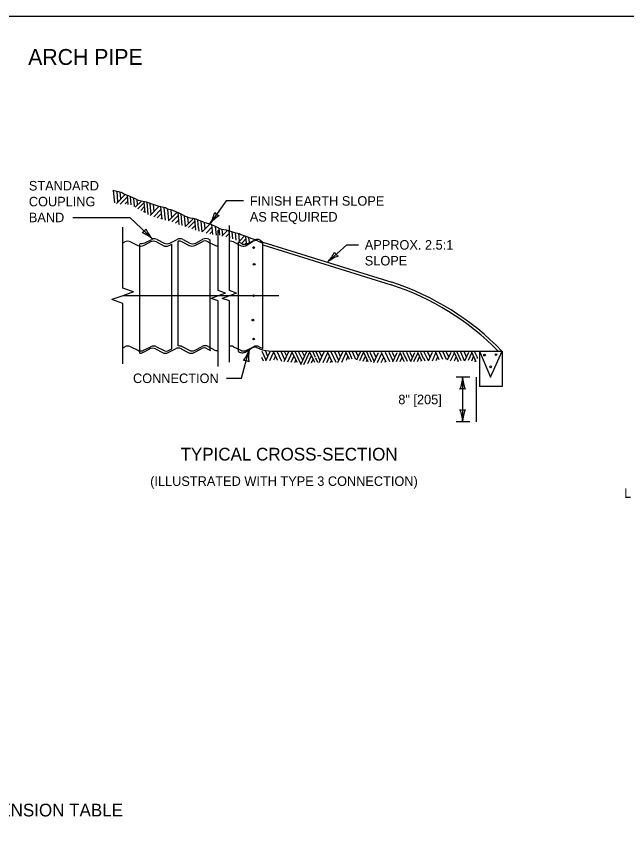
# Model space of a CAD drawing. Extents: x 49991.4 to 50021, y 49987.6 to 50011.4.
# Drawn here: x 50003.07 to 50006.92, y 49993.88 to 49999 of the extents above; entities that cross this region are included whole.
import ezdxf

# ---------------------------------------------------------------- set-up
doc = ezdxf.new("R2010")
doc.units = 0
for name, color, linetype in [('Level 1', 7, 'Continuous'), ('Level 2', 7, 'Continuous'), ('Level 3', 7, 'Continuous'), ('Level 4', 7, 'Continuous'), ('Level 5', 7, 'Continuous'), ('Level 6', 7, 'Continuous')]:
    doc.layers.add(name, color=color, linetype=linetype)

msp = doc.modelspace()

# ---------------------------------------------------------------- linework, layer by layer
at = {"layer": 'Level 1'}
for p, q in [((50003.6903, 49997.8225), (50003.6832, 49997.901)), ((50003.7012, 49997.8187), (50003.7579, 49997.8769)), ((50003.7109, 49997.8295), (50003.7049, 49997.8954)), ((50003.7292, 49997.8481), (50003.7252, 49997.8918)), ((50003.7755, 49997.8133), (50003.7702, 49997.87)), ((50003.7252, 49997.8141), (50003.7709, 49997.8607)), ((50003.7571, 49997.8164), (50003.7736, 49997.834)), ((50003.794, 49997.8104), (50003.7893, 49997.8613)), ((50003.8147, 49997.7995), (50003.8101, 49997.8529)), ((50003.82, 49997.7953), (50003.8584, 49997.8345)), ((50003.8347, 49997.8105), (50003.8318, 49997.844)), ((50003.8356, 49997.7853), (50003.8755, 49997.8256)), ((50003.8818, 49997.7611), (50003.8753, 49997.8285)), ((50003.8985, 49997.7802), (50003.8942, 49997.8244)), ((50003.92, 49997.7506), (50003.9133, 49997.8175)), ((50003.8546, 49997.7751), (50003.8785, 49997.8001)), ((50003.8727, 49997.7661), (50003.8803, 49997.7745)), ((50003.9016, 49997.7506), (50003.8992, 49997.7761)), ((50003.914, 49997.7445), (50003.97, 49997.8019)), ((50003.9381, 49997.769), (50003.9347, 49997.8124)), ((50003.9365, 49997.7359), (50003.9827, 49997.783)), ((50003.9886, 49997.7203), (50003.9806, 49997.7985)), ((50004.0106, 49997.7148), (50004.0027, 49997.7924)), ((50004.0321, 49997.7124), (50004.0253, 49997.7823)), ((50004.0285, 49997.7094), (50004.0834, 49997.7652)), ((50004.0499, 49997.7314), (50004.0455, 49997.7774)), ((50003.9587, 49997.7287), (50003.9853, 49997.7556)), ((50003.9819, 49997.7224), (50003.9874, 49997.7287)), ((50004.0507, 49997.7025), (50004.0911, 49997.7443)), ((50004.0735, 49997.6956), (50004.0942, 49997.717)), ((50004.097, 49997.6873), (50004.0898, 49997.7625)), ((50004.1159, 49997.6807), (50004.109, 49997.7514)), ((50004.1367, 49997.6738), (50004.13, 49997.7402)), ((50004.1361, 49997.6735), (50004.1865, 49997.7254)), ((50004.1555, 49997.6933), (50004.1517, 49997.7307)), ((50004.2016, 49997.6516), (50004.1955, 49997.7216)), ((50004.2189, 49997.6635), (50004.2146, 49997.7148)), ((50004.096, 49997.6878), (50004.0975, 49997.6894)), ((50004.1551, 49997.6669), (50004.1961, 49997.7091)), ((50004.1759, 49997.6598), (50004.1984, 49997.6832)), ((50004.2229, 49997.6456), (50004.2208, 49997.6652)), ((50004.2418, 49997.6398), (50004.2353, 49997.7065)), ((50004.2418, 49997.6398), (50004.2906, 49997.6902)), ((50004.2598, 49997.6584), (50004.2565, 49997.6974)), ((50004.2659, 49997.6328), (50004.3041, 49997.672)), ((50004.3088, 49997.6233), (50004.3027, 49997.6858)), ((50004.3305, 49997.619), (50004.3252, 49997.6747)), ((50004.3517, 49997.62), (50004.3474, 49997.6641)), ((50004.1972, 49997.653), (50004.201, 49997.6575)), ((50004.2896, 49997.627), (50004.3067, 49997.6444)), ((50004.3654, 49997.6129), (50004.4005, 49997.6496)), ((50004.3714, 49997.62), (50004.3682, 49997.6557)), ((50004.3893, 49997.6084), (50004.4133, 49997.6328)), ((50004.4165, 49997.6005), (50004.4117, 49997.6461)), ((50004.435, 49997.5958), (50004.4307, 49997.6399)), ((50004.456, 49997.5885), (50004.4515, 49997.6345)), ((50004.4769, 49997.5823), (50004.4727, 49997.6298)), ((50004.474, 49997.579), (50004.508, 49997.6144)), ((50004.5207, 49997.5668), (50004.5169, 49997.6118)), ((50003.7405, 49997.5698), (50003.7544, 49997.5769)), ((50003.7904, 49997.577), (50003.8354, 49997.5548)), ((50003.8716, 49997.5548), (50003.9161, 49997.5769)), ((50003.8792, 49997.571), (50003.924, 49997.5931)), ((50003.9529, 49997.5769), (50003.9959, 49997.5548)), ((50003.9581, 49997.5919), (50004.0017, 49997.5694)), ((50004.0329, 49997.5548), (50004.0501, 49997.5632)), ((50004.0384, 49997.5694), (50004.0833, 49997.593)), ((50004.0499, 49996.9024), (50004.0499, 49997.5632)), ((50004.0905, 49996.9211), (50004.0905, 49997.5817)), ((50004.1151, 49997.5774), (50004.1585, 49997.5548)), ((50004.1206, 49997.5926), (50004.1638, 49997.5698)), ((50004.1955, 49997.5548), (50004.2406, 49997.5783)), ((50004.2013, 49997.5698), (50004.2459, 49997.5936)), ((50004.2779, 49997.5783), (50004.321, 49997.5561)), ((50004.2832, 49997.5936), (50004.2926, 49997.5886)), ((50004.4192, 49997.5816), (50004.4125, 49997.5806)), ((50004.4377, 49997.5774), (50004.483, 49997.5548)), ((50004.4691, 49997.5769), (50004.49, 49997.566)), ((50004.4695, 49996.8871), (50004.4695, 49997.5767)), ((50004.4924, 49997.5716), (50004.5178, 49997.598)), ((50004.5141, 49997.5657), (50004.5203, 49997.5722)), ((50004.5179, 49997.5544), (50004.5577, 49997.5788)), ((50004.5265, 49997.566), (50004.537, 49997.5712)), ((50004.5386, 49997.5754), (50004.5359, 49997.6034)), ((50004.5376, 49997.5716), (50004.5712, 49997.5886)), ((50004.5602, 49997.5966), (50004.5727, 49997.5915)), ((50004.5899, 49997.5835), (50004.6085, 49997.5759)), ((50004.6073, 49997.5886), (50004.6232, 49997.5759)), ((50004.6085, 49997.5759), (50004.6232, 49997.5686)), ((50004.6232, 49997.5759), (50005.4359, 49997.3226)), ((50004.6232, 49997.5593), (50005.4308, 49997.3069)), ((50003.7407, 49996.9091), (50003.7547, 49996.9159)), ((50003.791, 49996.9159), (50003.8363, 49996.894)), ((50003.8667, 49996.8799), (50003.9107, 49996.9022)), ((50003.8722, 49996.894), (50003.917, 49996.9159)), ((50003.9478, 49996.9022), (50003.991, 49996.8799)), ((50003.953, 49996.9159), (50003.9968, 49996.894)), ((50004.0277, 49996.8799), (50004.0727, 49996.9031)), ((50004.0335, 49996.894), (50004.0499, 49996.9022)), ((50004.1099, 49996.903), (50004.1533, 49996.8804)), ((50004.1159, 49996.9168), (50004.1589, 49996.894)), ((50004.1908, 49996.8804), (50004.2355, 49996.9037)), ((50004.1966, 49996.894), (50004.2413, 49996.9175)), ((50004.2731, 49996.9037), (50004.2938, 49996.893)), ((50004.2789, 49996.9175), (50004.3219, 49996.8956)), ((50004.4383, 49996.9165), (50004.4837, 49996.894)), ((50004.5117, 49996.8824), (50004.5511, 49996.9067)), ((50004.5201, 49996.894), (50004.5308, 49996.8995)), ((50004.531, 49996.8995), (50004.565, 49996.9165)), ((50004.5832, 49996.9115), (50004.6021, 49996.9043)), ((50004.6009, 49996.9165), (50004.6232, 49996.905)), ((50003.848, 49996.8757), (50003.8494, 49996.8757)), ((50004.4691, 49996.8864), (50004.4769, 49996.8827)), ((50004.4695, 49996.8864), (50004.4695, 49996.8871)), ((50004.6277, 49996.8246), (50004.6168, 49996.8488)), ((50004.6448, 49996.832), (50004.6191, 49996.8869)), ((50004.6552, 49996.8557), (50004.6413, 49996.8869)), ((50004.6425, 49996.8266), (50004.6699, 49996.8869)), ((50004.6683, 49996.8304), (50004.6928, 49996.8832)), ((50004.6791, 49996.8887), (50006.1298, 49996.8887)), ((50004.7164, 49996.8314), (50004.6906, 49996.8869)), ((50004.6931, 49996.8341), (50004.7043, 49996.8581)), ((50004.7434, 49996.8238), (50004.7145, 49996.8869)), ((50004.7625, 49996.8328), (50004.738, 49996.8869)), ((50004.7581, 49996.8226), (50004.7879, 49996.8869)), ((50004.7734, 49996.8566), (50004.7597, 49996.8869)), ((50004.78, 49996.8208), (50004.8089, 49996.8827)), ((50004.8023, 49996.8191), (50004.8201, 49996.8581)), ((50004.8397, 49996.8162), (50004.8069, 49996.8869)), ((50004.8634, 49996.8078), (50004.8267, 49996.8869)), ((50004.8742, 49996.8314), (50004.8485, 49996.8869)), ((50004.8621, 49996.8053), (50004.8997, 49996.8871)), ((50004.8855, 49996.856), (50004.8716, 49996.8869)), ((50004.8825, 49996.8053), (50004.9187, 49996.8844)), ((50004.9071, 49996.8107), (50004.93, 49996.8604)), ((50004.9508, 49996.8162), (50004.918, 49996.8869)), ((50004.9558, 49996.8488), (50004.9383, 49996.8869)), ((50004.9696, 49996.8162), (50004.9561, 49996.8451)), ((50004.984, 49996.8283), (50004.9587, 49996.8832)), ((50004.9786, 49996.8162), (50005.0092, 49996.8832)), ((50004.9951, 49996.8521), (50004.9807, 49996.8832)), ((50005.0026, 49996.8162), (50005.0321, 49996.8792)), ((50005.0259, 49996.8162), (50005.0438, 49996.8542)), ((50005.0615, 49996.8162), (50005.0307, 49996.8832)), ((50005.0849, 49996.8162), (50005.0543, 49996.8832)), ((50005.1019, 49996.8293), (50005.0775, 49996.8832)), ((50005.0963, 49996.8162), (50005.1274, 49996.8832)), ((50005.1128, 49996.853), (50005.0993, 49996.8832)), ((50005.1206, 49996.82), (50005.1479, 49996.879)), ((50005.1682, 49996.8356), (50005.1463, 49996.8832)), ((50005.1496, 49996.8325), (50005.1595, 49996.8542)), ((50005.1867, 49996.8389), (50005.1664, 49996.8832)), ((50005.2099, 49996.8356), (50005.1879, 49996.8832)), ((50005.2249, 49996.8524), (50005.2111, 49996.8832)), ((50005.2162, 49996.8336), (50005.2393, 49996.8833)), ((50005.2345, 49996.8293), (50005.2582, 49996.8805)), ((50005.2553, 49996.826), (50005.2696, 49996.8572)), ((50005.2858, 49996.8218), (50005.2571, 49996.8832)), ((50005.2954, 49996.8451), (50005.2775, 49996.8832)), ((50005.3253, 49996.8246), (50005.2996, 49996.8792)), ((50005.3217, 49996.8166), (50005.3509, 49996.8792)), ((50005.3362, 49996.8479), (50005.3221, 49996.8792)), ((50005.3456, 49996.8162), (50005.3733, 49996.8757)), ((50005.369, 49996.8166), (50005.3853, 49996.8508)), ((50005.3999, 49996.8185), (50005.3716, 49996.8792)), ((50005.4224, 49996.8206), (50005.395, 49996.8792)), ((50005.4435, 49996.8256), (50005.4188, 49996.8792)), ((50005.4541, 49996.8494), (50005.4404, 49996.8792)), ((50005.4413, 49996.8217), (50005.4683, 49996.8792)), ((50005.4645, 49996.8226), (50005.489, 49996.8752)), ((50005.5133, 49996.8235), (50005.4874, 49996.8792)), ((50005.4884, 49996.8235), (50005.5007, 49996.8508)), ((50005.5334, 49996.8235), (50005.5073, 49996.8792)), ((50005.5552, 49996.8238), (50005.5292, 49996.8792)), ((50005.5665, 49996.8485), (50005.5519, 49996.8792)), ((50005.5545, 49996.8235), (50005.5805, 49996.8794)), ((50005.5749, 49996.8235), (50005.5994, 49996.8768)), ((50005.597, 49996.8235), (50005.6102, 49996.8532)), ((50005.6239, 49996.8246), (50005.5989, 49996.8792)), ((50005.6361, 49996.8415), (50005.6191, 49996.8792)), ((50005.6458, 49996.8259), (50005.6373, 49996.8434)), ((50005.6657, 49996.8266), (50005.6401, 49996.8811)), ((50005.6765, 49996.8502), (50005.6623, 49996.8811)), ((50005.6657, 49996.8266), (50005.6909, 49996.8811)), ((50005.6908, 49996.8282), (50005.7137, 49996.8776)), ((50005.7343, 49996.8332), (50005.7121, 49996.8811)), ((50005.7149, 49996.8306), (50005.7254, 49996.8526)), ((50005.7562, 49996.8364), (50005.7356, 49996.8811)), ((50005.7795, 49996.8366), (50005.7587, 49996.8811)), ((50005.7943, 49996.8511), (50005.7808, 49996.8811)), ((50005.7872, 49996.8342), (50005.8088, 49996.8811)), ((50005.806, 49996.8266), (50005.8297, 49996.8769)), ((50005.8551, 49996.823), (50005.8275, 49996.8811)), ((50005.8297, 49996.8271), (50005.8412, 49996.8526)), ((50005.8732, 49996.8266), (50005.8478, 49996.8811)), ((50005.8943, 49996.8282), (50005.8697, 49996.8811)), ((50005.9066, 49996.8504), (50005.8923, 49996.8811)), ((50005.896, 49996.8282), (50005.9206, 49996.8818)), ((50005.9183, 49996.8319), (50005.9402, 49996.8788)), ((50005.9385, 49996.8282), (50005.951, 49996.8552)), ((50005.9662, 49996.8218), (50005.939, 49996.8811)), ((50005.9767, 49996.8434), (50005.9593, 49996.8811)), ((50005.9763, 49996.843), (50005.9741, 49996.8479)), ((50005.9883, 49996.8887), (50005.9883, 49996.6662)), ((50005.9883, 49996.8887), (50006.0569, 49996.7243)), ((50006.0569, 49996.7243), (50006.1298, 49996.8887)), ((50006.1298, 49996.8887), (50006.1298, 49996.6662)), ((50004.715, 49996.8319), (50004.7159, 49996.8335)), ((50004.8253, 49996.8174), (50004.8321, 49996.8326)), ((50004.9305, 49996.8151), (50004.9405, 49996.8376)), ((50005.0488, 49996.8162), (50005.0551, 49996.8299)), ((50005.2755, 49996.8234), (50005.2798, 49996.834)), ((50005.308, 49996.8184), (50005.2975, 49996.8415)), ((50005.393, 49996.8184), (50005.3961, 49996.826)), ((50005.5121, 49996.8235), (50005.5127, 49996.8253)), ((50005.6191, 49996.8244), (50005.6212, 49996.8299)), ((50005.8514, 49996.8235), (50005.8528, 49996.8271)), ((50005.9577, 49996.823), (50005.9619, 49996.8319)), ((50006.1298, 49996.6662), (50005.9883, 49996.6662))]:
    msp.add_line(p, q, dxfattribs=at)
msp.add_lwpolyline([(49999.3835, 49998.9992), (50016.7501, 49998.9992), (50016.7501, 49987.7988), (49999.3835, 49987.7988)], close=True, dxfattribs=at)
msp.add_lwpolyline([(50003.6779, 49997.9035), (50003.7311, 49997.891), (50003.7389, 49997.8864), (50003.7529, 49997.8784), (50003.775, 49997.8692), (50003.7859, 49997.8646), (50003.8062, 49997.8552), (50003.8157, 49997.8519), (50003.8375, 49997.8411), (50003.8579, 49997.8349), (50003.8891, 49997.8289), (50003.9001, 49997.8256), (50003.9235, 49997.8177), (50003.9439, 49997.8115), (50003.9626, 49997.8054), (50003.9892, 49997.7976), (50004.0111, 49997.7929), (50004.0237, 49997.785), (50004.0502, 49997.7788), (50004.0735, 49997.7697), (50004.091, 49997.7632), (50004.1111, 49997.7524), (50004.1345, 49997.7398), (50004.1644, 49997.729), (50004.1848, 49997.7272), (50004.2005, 49997.7227), (50004.2207, 49997.7133), (50004.2581, 49997.6994), (50004.2818, 49997.6932), (50004.2911, 49997.69), (50004.3271, 49997.6744), (50004.3567, 49997.659), (50004.3786, 49997.6557), (50004.3927, 49997.6526), (50004.4396, 49997.6384), (50004.4741, 49997.6292), (50004.4851, 49997.623), (50004.5225, 49997.6105), (50004.5476, 49997.5997), (50004.5602, 49997.5966)], dxfattribs=at)
for centre, radius in [((50004.5655, 49997.5413), 0.00558), ((50004.5689, 49997.4357), 0.00558), ((50004.5655, 49997.2381), 0.00558), ((50004.5608, 49997.0845), 0.00558), ((50004.5655, 49996.9649), 0.00558), ((50006.0197, 49996.8639), 0.00557), ((50006.0918, 49996.8667), 0.00557), ((50006.0583, 49996.7899), 0.00557)]:
    msp.add_circle(centre, radius, dxfattribs=at)
for centre, radius, start, end in [((50003.7723, 49997.5407), 0.0405, 63.5216, 116.8449), ((50003.8611, 49997.6072), 0.0405, 251.8711, 296.6032), ((50003.9342, 49997.5407), 0.0405, 62.9182, 116.6003), ((50003.9396, 49997.5557), 0.0405, 62.9182, 112.7334), ((50004.0198, 49997.6056), 0.0405, 242.9112, 297.1838), ((50004.1019, 49997.5568), 0.0405, 62.3296, 117.1813), ((50004.0964, 49997.5417), 0.0405, 62.3296, 98.166), ((50004.1826, 49997.6058), 0.0405, 242.3292, 297.6433), ((50004.2593, 49997.5425), 0.0405, 62.5543, 117.6538), ((50004.2648, 49997.5576), 0.0405, 62.5543, 117.6538), ((50004.4198, 49997.541), 0.0405, 63.6272, 91.014), ((50004.5082, 49997.6023), 0.0405, 243.619, 283.116), ((50004.5082, 49997.6023), 0.0405, 286.7943, 296.6877), ((50004.5788, 49997.5445), 0.0405, 74.5382, 121.9141), ((50004.5892, 49997.5524), 0.0405, 63.1956, 116.6972), ((50003.8534, 49997.5907), 0.0405, 243.5224, 296.6032), ((50004.0144, 49997.5905), 0.0405, 242.9112, 297.1838), ((50004.1771, 49997.5907), 0.0405, 242.3292, 297.6433), ((50004.3395, 49997.592), 0.0405, 242.558, 274.6236), ((50004.5011, 49997.591), 0.0405, 243.619, 283.116), ((50004.5011, 49997.591), 0.0405, 286.7943, 296.2055), ((50004.9072, 49995.7069), 1.6834, 44.5892, 71.8806), ((50004.9072, 49995.7069), 1.7, 44.0403, 71.8806), ((50003.773, 49996.88), 0.0405, 63.5216, 116.8449), ((50003.9291, 49996.8661), 0.0405, 62.9182, 116.6003), ((50003.9349, 49996.8799), 0.0405, 62.9182, 116.6003), ((50004.0913, 49996.8671), 0.0405, 62.3296, 117.1813), ((50004.0971, 49996.8809), 0.0405, 62.3296, 99.3453), ((50004.2542, 49996.8679), 0.0405, 62.5543, 117.6538), ((50004.2601, 49996.8817), 0.0405, 62.5543, 117.6538), ((50004.3403, 49996.9313), 0.0405, 242.558, 272.8099), ((50004.4205, 49996.8803), 0.0405, 63.6272, 101.0088), ((50004.5725, 49996.8724), 0.0405, 74.5382, 121.9141), ((50004.5828, 49996.8804), 0.0405, 63.1956, 116.6972), ((50004.6792, 49997.091), 0.2023, 247.5327, 270), ((50003.8541, 49996.93), 0.0405, 243.5224, 261.4108), ((50003.8541, 49996.93), 0.0405, 261.7501, 296.6032), ((50003.8483, 49996.9161), 0.0405, 271.3626, 296.6032), ((50004.0093, 49996.916), 0.0405, 242.9112, 297.1838), ((50004.0151, 49996.9298), 0.0405, 242.9112, 297.1838), ((50004.172, 49996.9162), 0.0405, 242.3292, 297.6433), ((50004.1778, 49996.93), 0.0405, 242.3292, 297.6433), ((50004.4948, 49996.919), 0.0405, 243.619, 283.116), ((50004.5019, 49996.9303), 0.0405, 243.619, 283.116), ((50004.4948, 49996.919), 0.0405, 286.7943, 296.2055), ((50004.5019, 49996.9303), 0.0405, 286.7943, 296.6877), ((50004.6363, 49996.0796), 0.8092, 90, 90.0000333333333)]:
    msp.add_arc(centre, radius, start, end, dxfattribs=at)
at = {"layer": 'Level 3'}
for p, q in [((50004.3932, 49997.8352), (50004.2893, 49997.6906)), ((50004.5013, 49997.8352), (50004.3932, 49997.8352)), ((50003.4257, 49997.7311), (50003.7851, 49997.7311)), ((50003.7851, 49997.7311), (50003.9298, 49997.595)), ((50005.1532, 49997.5585), (50005.0295, 49997.4493)), ((50005.1532, 49997.5585), (50005.2254, 49997.5585)), ((50004.4896, 49996.7175), (50004.5382, 49996.8988)), ((50004.3953, 49996.7175), (50004.4896, 49996.7175)), ((50005.9273, 49996.7243), (50005.8415, 49996.7243)), ((50005.8815, 49996.7243), (50005.8815, 49996.4436)), ((50005.9273, 49996.4436), (50005.8415, 49996.4436))]:
    msp.add_line(p, q, dxfattribs=at)
for centre, radius, start, end in [((50004.0936, 49997.8171), 0.233, 327.1361, 346.386), ((50004.4644, 49997.5536), 0.2223, 121.7648, 141.9484), ((50004.3641, 49997.7948), 0.0548, 216.4477, 252.17), ((50003.8364, 49997.6828), 0.0548, 298.8966, 334.619), ((50003.7788, 49997.4176), 0.233, 49.5851, 68.8349), ((50004.0887, 49997.7505), 0.2223, 204.2138, 224.3973), ((50004.8668, 49997.616), 0.233, 314.2908, 333.5406), ((50005.1256, 49997.5342), 0.0548, 203.6023, 239.3247), ((50005.1697, 49997.2767), 0.2223, 108.9195, 129.103), ((50004.3261, 49996.9652), 0.2223, 322.4499, 342.6334), ((50004.766, 49996.8497), 0.233, 167.8212, 187.071), ((50004.5051, 49996.775), 0.0548, 57.1327, 92.855), ((50005.6593, 49996.7335), 0.2223, 337.456, 357.6395), ((50006.1142, 49996.7358), 0.233, 182.8273, 202.0772), ((50005.8815, 49996.5961), 0.0548, 72.1388, 107.8612), ((50005.8815, 49996.5718), 0.0548, 252.1388, 287.8612), ((50005.6488, 49996.4321), 0.233, 2.8273, 22.0772), ((50006.1036, 49996.4345), 0.2223, 157.456, 177.6395)]:
    msp.add_arc(centre, radius, start, end, dxfattribs=at)
at = {"layer": 'Level 4'}
for p, q in [((50003.848, 49996.8757), (50003.848, 49997.5631)), ((50004.2926, 49996.8973), (50004.2926, 49997.5889)), ((50004.6232, 49996.905), (50004.6232, 49997.5762)), ((50004.6232, 49997.381), (50004.6232, 49997.3828)), ((50004.6232, 49997.0917), (50004.6232, 49997.0922)), ((50005.9673, 49996.7243), (50005.9673, 49996.4436))]:
    msp.add_line(p, q, dxfattribs=at)
at = {"layer": 'Level 5'}
msp.add_line((50004.7232, 49997.2374), (50003.7407, 49997.2374), dxfattribs=at)
at = {"layer": 'Level 6'}
for p, q in [((50003.7407, 49997.286), (50003.7407, 49997.6699)), ((50004.4125, 49997.2698), (50004.4125, 49997.6806)), ((50004.3427, 49997.2698), (50004.3427, 49997.6517)), ((50003.8092, 49997.2617), (50003.7407, 49997.286)), ((50003.8092, 49997.2617), (50003.7407, 49997.2374)), ((50004.3884, 49997.2536), (50004.3427, 49997.2698)), ((50004.3884, 49997.2536), (50004.3427, 49997.2374)), ((50004.4582, 49997.2536), (50004.4125, 49997.2698)), ((50004.4582, 49997.2536), (50004.4125, 49997.2374)), ((50003.7407, 49997.2374), (50003.6722, 49997.2131)), ((50003.7407, 49997.1888), (50003.6722, 49997.2131)), ((50004.3427, 49997.2374), (50004.297, 49997.2212)), ((50004.3427, 49997.205), (50004.297, 49997.2212)), ((50004.3427, 49996.7909), (50004.3427, 49997.205)), ((50004.4125, 49997.2374), (50004.3668, 49997.2212)), ((50004.4125, 49997.205), (50004.3668, 49997.2212)), ((50004.4125, 49996.8199), (50004.4125, 49997.205)), ((50003.7407, 49996.8091), (50003.7407, 49997.1888))]:
    msp.add_line(p, q, dxfattribs=at)

# ---------------------------------------------------------------- texts
at = {"layer": 'Level 2'}
for s, height, p in [('ARCH PIPE', 0.1, (50003.1455, 49998.6926)), ('STANDARD', 0.06, (50003.1498, 49997.9011)), ('COUPLING', 0.06, (50003.1498, 49997.8011)), ('FINISH EARTH SLOPE', 0.06, (50004.5413, 49997.8052)), ('AS REQUIRED', 0.06, (50004.5413, 49997.7052)), ('BAND', 0.06, (50003.1498, 49997.7011)), ('APPROX. 2.5:1', 0.06, (50005.2654, 49997.5285)), ('SLOPE', 0.06, (50005.2654, 49997.4285)), ('CONNECTION', 0.06, (50003.8058, 49996.6875)), ('8" [205]', 0.06, (50005.4765, 49996.554)), ('TYPICAL CROSS-SECTION', 0.08, (50004.105, 49996.1993)), ('(ILLUSTRATED WITH TYPE 3 CONNECTION)', 0.06, (50003.914, 49996.0393)), ('L', 0.06, (50006.8987, 49995.9639)), ('DIMENSION TABLE', 0.08, (50002.7677, 49993.9561))]:
    msp.add_text(s, height=height, dxfattribs=at).set_placement(p)

doc.saveas('drawing.dxf')
